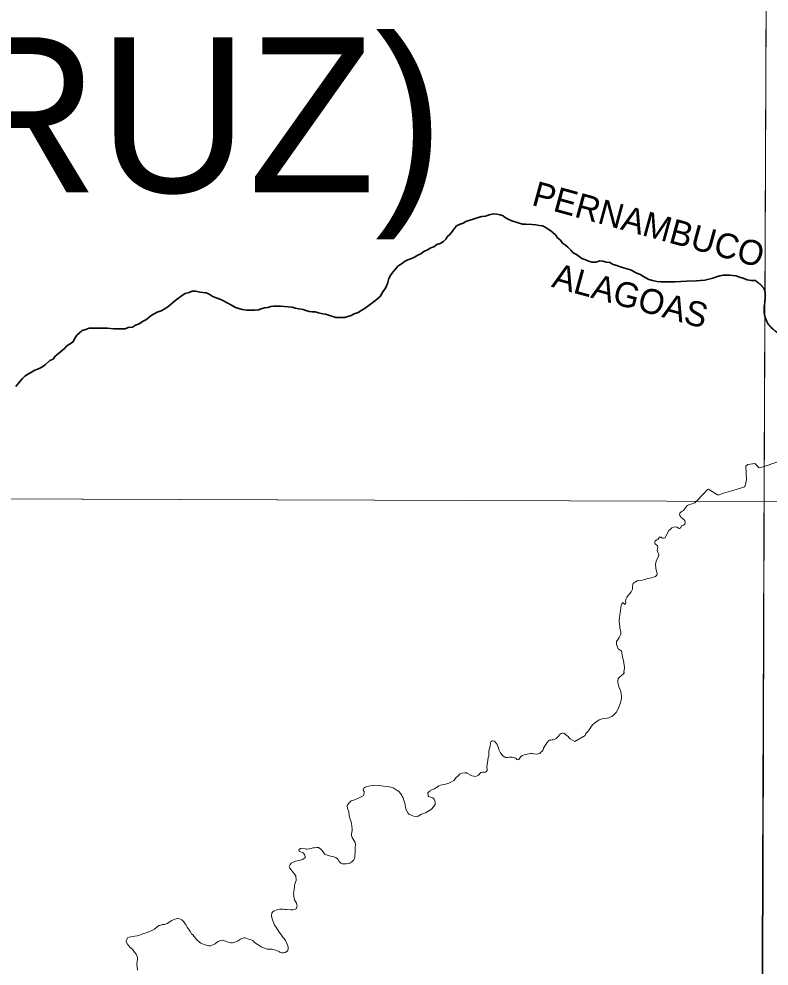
# Model space of a CAD drawing. Extents: x 553962 to 842807, y 8883888 to 9032388.
# Drawn here: x 594238 to 596656, y 8919494 to 8922544 of the extents above; entities that cross this region are included whole.
import ezdxf
from ezdxf.enums import TextEntityAlignment as Align

# ---------------------------------------------------------------- set-up
doc = ezdxf.new("R2010")
doc.units = 0
doc.header["$LTSCALE"] = 200
doc.linetypes.add('LONG_DASH_SHORT_DASH', pattern=[9.9, 6, -1.2, 1.5, -1.2])
doc.layers.add('6', color=7, linetype='Continuous', lineweight=13)

msp = doc.modelspace()

# ---------------------------------------------------------------- linework, layer by layer
at = {"layer": '6'}
for points in [[(585656.3, 8924738.8), (596655.5, 8924715.8), (596639.8, 8920989.8), (585645.8, 8921027.3)], [(607600.8, 8920952.4), (596639.8, 8920989.8), (596608.8, 8909934.4), (607569.8, 8909894.9)]]:
    msp.add_lwpolyline(points, close=True, dxfattribs=at)
for points in [[(596655.5, 8924715.8), (596593.3, 8909930.3), (596531.7, 8896026.7)], [(596581.2, 8921103.5), (596583.4, 8921058), (596577.4, 8921038.4), (596576.5, 8921036.9), (596546.9, 8921026.8), (596509.1, 8921016.7), (596491.7, 8921010.3), (596490, 8921010.8), (596472.1, 8921022.3), (596460.7, 8921029.2), (596459.6, 8921029.6), (596457.7, 8921028), (596445.2, 8921015.4), (596419.5, 8920988.9)], [(596684.4, 8921117.9), (596636.5, 8921101.1), (596623.7, 8921097.9), (596609.9, 8921111.7), (596587.7, 8921108.9), (596581.2, 8921103.5)], [(574684.9, 8921064.7), (596639.8, 8920989.8), (607636.3, 8920937.2), (626625.7, 8920820.5)], [(596419.5, 8920988.9), (596416.1, 8920985.5), (596411.6, 8920983.1), (596407.8, 8920981.7), (596399.5, 8920980), (596392.7, 8920976.5), (596389.8, 8920974.2), (596389.4, 8920973.2), (596388.5, 8920972.8), (596388, 8920971.8), (596387, 8920970.8), (596385.5, 8920968), (596383.2, 8920964.5), (596380.2, 8920960.7), (596376.2, 8920958.1), (596372.5, 8920956.2), (596369.6, 8920953.6), (596368.4, 8920952), (596367.4, 8920948.3), (596368.1, 8920946.1), (596368.2, 8920944.4), (596370, 8920941.5), (596371.9, 8920939.1), (596374.2, 8920937.3), (596377.3, 8920934.5), (596381, 8920931.9), (596384.8, 8920927.5), (596384.8, 8920927.5), (596385.6, 8920924.6), (596383.9, 8920916.4), (596383.6, 8920915.6), (596379.7, 8920913.5), (596373.2, 8920911.8), (596371.3, 8920906.5), (596370.2, 8920904.4), (596367.6, 8920903.1), (596364.1, 8920903.5), (596358.3, 8920907.2), (596357.3, 8920907.5), (596352.8, 8920907.7), (596347.5, 8920907.1), (596342.6, 8920904.7), (596337.1, 8920900), (596333.1, 8920895.9), (596322.9, 8920878.2)], [(596322.9, 8920878.2), (596321.8, 8920875.5), (596320.5, 8920873.2), (596315.8, 8920871.4), (596312.6, 8920871.3), (596310.4, 8920872.7), (596308.4, 8920874.5), (596303, 8920874.9), (596298.1, 8920868.6), (596293.7, 8920866.1), (596288.5, 8920862.6), (596287.3, 8920858.1), (596287.3, 8920855.8), (596289.2, 8920853.1), (596295.7, 8920846.8), (596296.2, 8920845.8), (596296.8, 8920842.9), (596295, 8920832), (596300.2, 8920819.4), (596299.3, 8920813.8), (596292.4, 8920797.3), (596290.7, 8920791.7), (596289.4, 8920786.3), (596290.7, 8920775), (596292.3, 8920769.4), (596293.4, 8920763.9), (596295.3, 8920758.3), (596294.3, 8920752.9), (596293.5, 8920751), (596289.7, 8920748.2), (596275.6, 8920744), (596269.9, 8920743.1), (596264.5, 8920741.9), (596258.8, 8920739.7), (596253.2, 8920738.4), (596247.6, 8920736.7), (596236.5, 8920735.2), (596230.9, 8920733.7), (596225.4, 8920731.3), (596218.8, 8920726.5), (596218.2, 8920725.5), (596216.7, 8920722.2), (596215.8, 8920715.7), (596215.7, 8920710.1), (596215.3, 8920707.1), (596211.6, 8920699.2), (596197.7, 8920682), (596193.8, 8920675.4), (596193.1, 8920667.7), (596194.2, 8920664.1), (596192.8, 8920660.7), (596192.2, 8920658.1), (596192, 8920658), (596185.8, 8920663.5), (596183.3, 8920663.3), (596181.1, 8920659.8), (596179.3, 8920654.3), (596178.1, 8920648.7), (596176.8, 8920637.8), (596175.7, 8920632), (596175.2, 8920626.1), (596173.4, 8920615.3), (596172.7, 8920609.8), (596172.8, 8920603.6), (596174.4, 8920586.9), (596175.3, 8920581.1), (596177.2, 8920575.1), (596177.8, 8920569.5), (596177.6, 8920563.3), (596177.3, 8920560), (596173.2, 8920551.4), (596169.7, 8920546), (596164.5, 8920539), (596163.8, 8920534.7), (596164.4, 8920529.3), (596165.8, 8920523.5), (596169.8, 8920515.6), (596179, 8920508.3), (596179.7, 8920507.3), (596181.2, 8920501.9), (596182.2, 8920495.7), (596184.6, 8920484.3), (596186.5, 8920477.5), (596189.9, 8920455.4)], [(596189.9, 8920455.4), (596189.5, 8920454.3), (596187.2, 8920440.2), (596187.2, 8920439.4), (596188.3, 8920437.7), (596188.3, 8920437.1), (596185.5, 8920433.8), (596181.5, 8920430.2), (596172.4, 8920423), (596169.5, 8920418.8), (596168.2, 8920412.8), (596168.7, 8920407.7), (596169.5, 8920402.7), (596172, 8920392.7), (596176.5, 8920381.4), (596178, 8920376.9), (596179.2, 8920371.6), (596180.6, 8920361.1), (596180.6, 8920356.3), (596179.6, 8920351.4), (596176.7, 8920340.8), (596168, 8920320.1), (596162.5, 8920310), (596158.8, 8920305.4), (596153.7, 8920300.7), (596148.8, 8920297.3), (596144, 8920294.9), (596139.2, 8920293.3), (596128.6, 8920290.9), (596118.2, 8920289.7), (596108.2, 8920286.6), (596097.6, 8920278.6)], [(596097.6, 8920278.6), (596087, 8920270.7), (596086.2, 8920270.4), (596080.9, 8920262.8), (596078.5, 8920257.9), (596076, 8920254.4), (596072.4, 8920250.1), (596065.8, 8920243.2), (596064.1, 8920240.6), (596063, 8920236.2), (596030, 8920216.7), (596014.6, 8920225.9), (596013.7, 8920226.2), (596013.1, 8920226.8), (596012.8, 8920227.7), (596010.9, 8920229.4), (596007.9, 8920232.8), (596000.2, 8920239.7), (595996.7, 8920242.2), (595992.4, 8920243.5), (595988.7, 8920243.2), (595985.4, 8920242.5), (595983.7, 8920241.8), (595981.6, 8920239.6), (595976.4, 8920232.6), (595973.2, 8920229.4), (595969.3, 8920226.3), (595963.4, 8920223.6), (595959.7, 8920222.4), (595955.7, 8920221.9), (595952, 8920221.1), (595948.5, 8920221.1), (595947.7, 8920220.8), (595944.7, 8920218.6), (595940.5, 8920213.8), (595940.1, 8920212.7), (595939.1, 8920212), (595936.7, 8920206.9)], [(595936.7, 8920206.9), (595936.6, 8920206.9), (595929.1, 8920195.6), (595929.2, 8920192.4), (595927.8, 8920190.1), (595924, 8920185.5), (595919.5, 8920180.9), (595916.5, 8920178.5), (595912.4, 8920177.2), (595907.3, 8920176.2), (595897.2, 8920177), (595891.9, 8920177.8), (595886.4, 8920177.8), (595881.6, 8920177.2), (595866.2, 8920173.5), (595861.1, 8920171.8), (595856.2, 8920168.8), (595848.9, 8920158.8), (595845, 8920158), (595843.1, 8920159.2), (595839.4, 8920163), (595833.5, 8920165.6), (595828.2, 8920166.5), (595818.6, 8920165.9), (595813.1, 8920165), (595806.4, 8920165.6), (595802.8, 8920167.3), (595797.3, 8920170.8), (595790.6, 8920180), (595786.8, 8920186.4), (595784.7, 8920191.3), (595784, 8920196.7), (595782.1, 8920201.6), (595779.5, 8920206.9), (595776.4, 8920211.9), (595772.8, 8920216), (595770, 8920218), (595764.9, 8920219.3), (595762.9, 8920219.2), (595760.1, 8920216.5), (595757.9, 8920212.1), (595756.5, 8920201.4), (595753, 8920186.6), (595752.3, 8920180.9), (595752.1, 8920171), (595750.8, 8920165.7), (595749.5, 8920155.6), (595748.2, 8920150.3), (595746.6, 8920135.4), (595747, 8920125.1), (595746.8, 8920123), (595744.1, 8920119), (595741.7, 8920117.9), (595733.7, 8920117.9), (595729, 8920117.3), (595726.8, 8920116.5), (595726.1, 8920116), (595719.5, 8920108.7), (595714.6, 8920105.7), (595709.3, 8920104.6), (595704.2, 8920104.7), (595697.4, 8920106.1), (595682.2, 8920114.9), (595680.4, 8920115.5), (595675.5, 8920115.9), (595665.3, 8920114.4), (595660.3, 8920112.3), (595658.1, 8920111)], [(595658.1, 8920111), (595655.6, 8920108.5), (595651.9, 8920104.2), (595647.8, 8920100.6), (595639.3, 8920091), (595632.7, 8920087), (595623.2, 8920082.6), (595617.5, 8920080.8), (595612.7, 8920078.9), (595606.8, 8920078.2), (595597.1, 8920075.8), (595591.6, 8920073.9), (595586.7, 8920071), (595581.7, 8920067.6), (595577.1, 8920064.8), (595571.5, 8920062.6), (595561.7, 8920056.4), (595561.7, 8920056.4), (595556.2, 8920051.1)], [(595556.2, 8920051.1), (595556.8, 8920041.8), (595557.1, 8920040.8), (595558.3, 8920039.9), (595568.7, 8920036.2), (595571.6, 8920035), (595576.8, 8920030.7), (595578.9, 8920025.4), (595579.7, 8920020.2), (595579.8, 8920016.6), (595579.2, 8920014.4), (595568.5, 8919999.7), (595567.3, 8919998.5), (595548.1, 8919986.8), (595541.1, 8919985.3), (595535.4, 8919982.4), (595524.6, 8919976), (595518.6, 8919974.3), (595513.3, 8919975), (595502.3, 8919979.2), (595495.2, 8919983.1), (595491.5, 8919987.2), (595486.8, 8919994.6), (595485.2, 8920000.2), (595484.5, 8920006.3), (595481.8, 8920018), (595479.4, 8920024.2), (595478.1, 8920030.1), (595476.1, 8920035.8), (595474.8, 8920037.4), (595472.3, 8920042.5), (595468.9, 8920048.1), (595462.9, 8920056.2), (595457.2, 8920059.5), (595444.2, 8920067.7), (595436.6, 8920069.9), (595431.2, 8920071), (595425.4, 8920071.8), (595413.3, 8920072.9), (595407.1, 8920073.8), (595395.5, 8920074.6), (595383.1, 8920075.9), (595377.1, 8920075.5), (595365.3, 8920073.2), (595359.7, 8920071.7), (595353.5, 8920068.5), (595349.8, 8920066.3), (595348.4, 8920064.4), (595347.6, 8920062.5), (595348.1, 8920060.6), (595350.5, 8920055.3), (595350.7, 8920050.2), (595349.1, 8920044.4), (595347.4, 8920041.8), (595332.8, 8920034.6), (595319.8, 8920029.3), (595308.8, 8920025.2), (595303.6, 8920020.4), (595296.8, 8920012.5), (595296.3, 8920010.1), (595296.8, 8920002), (595298.6, 8919998.5), (595301.1, 8919990.6), (595302.4, 8919978.8), (595303.5, 8919972.9), (595306.1, 8919966.4), (595309.8, 8919954.2), (595311.2, 8919942.8), (595312.2, 8919936.4), (595312.2, 8919930.6), (595310.5, 8919919.3), (595310.5, 8919914.1), (595312, 8919907.4), (595321.5, 8919891.2), (595322.7, 8919885.4), (595322.1, 8919874.5), (595322.3, 8919868.3), (595321.6, 8919856.8), (595320.8, 8919850.8), (595321, 8919844.9), (595319.8, 8919839.6), (595317.8, 8919835.8), (595315.7, 8919833.1), (595311, 8919828.8), (595304.7, 8919824.7), (595293.7, 8919822.5), (595287.7, 8919822.5), (595281.7, 8919822.9), (595279.6, 8919823.3), (595276.1, 8919825.3), (595270.4, 8919830.6), (595265.5, 8919837.5), (595259.1, 8919843.4), (595253.4, 8919845.2), (595241.8, 8919847.7), (595235.8, 8919849.4), (595229.3, 8919851.8), (595224.2, 8919853.9), (595221.7, 8919855.6), (595215.5, 8919865.8), (595211.5, 8919869.9)], [(595211.5, 8919869.9), (595211.5, 8919869.9), (595203.4, 8919875.3), (595196.7, 8919875.5), (595191.1, 8919874.5), (595185.1, 8919873.9), (595179.1, 8919872.2), (595173.5, 8919871.2), (595167, 8919870.5), (595163.5, 8919870.5), (595160.9, 8919871.1), (595149.3, 8919873), (595145.9, 8919872.6), (595141.2, 8919869.2), (595140.4, 8919866.2), (595140.9, 8919864.8), (595142, 8919862.9), (595154.1, 8919858.3), (595158.4, 8919853), (595159.9, 8919850), (595160.5, 8919846.3), (595160.3, 8919843.4), (595158.2, 8919840.8), (595152.4, 8919836.5), (595141.6, 8919833.3), (595135.4, 8919832.3), (595129.5, 8919831.1), (595122.5, 8919828.4), (595116, 8919824.6), (595113.1, 8919821.6), (595112.2, 8919820.4), (595109.5, 8919814.4), (595109.6, 8919812.9), (595111.6, 8919808.8), (595130.3, 8919784.6), (595131.4, 8919769.3), (595127.8, 8919758.5), (595126.5, 8919753.3), (595126, 8919748), (595123.7, 8919733.2), (595123.5, 8919727.1), (595123.7, 8919722.3), (595124.3, 8919717.4), (595126.6, 8919707.1), (595129.1, 8919701.7), (595132.3, 8919696.5), (595134.2, 8919691.2), (595134.9, 8919686.4), (595133.1, 8919680.8), (595132.3, 8919679.5), (595128.7, 8919677), (595125.3, 8919675.6), (595120.4, 8919674.8), (595115, 8919674.6), (595100.3, 8919676.1), (595094.8, 8919676.1), (595089.5, 8919676.5), (595084.5, 8919676.3), (595079.2, 8919676.5), (595069.2, 8919674.8), (595059.4, 8919670.2), (595055.8, 8919667.6), (595053.5, 8919663.7), (595052, 8919657.7), (595052.1, 8919654.1), (595055.6, 8919642.4), (595057.9, 8919637.1), (595059.3, 8919631.8), (595061.3, 8919625.8), (595063.1, 8919624.4), (595064.1, 8919622.7), (595069.5, 8919614.9), (595072.4, 8919609.9), (595076.3, 8919605.2), (595080.2, 8919598.6), (595084.2, 8919593.5), (595088.7, 8919586.8), (595092.6, 8919582.8), (595096.9, 8919576.3), (595099.5, 8919571.6), (595104.2, 8919560.8), (595105.8, 8919556), (595106, 8919550.3), (595104.9, 8919544.2), (595104.4, 8919543.4), (595101.4, 8919540.4), (595096.4, 8919537.1), (595091.3, 8919536.3), (595085.6, 8919536.5), (595079.3, 8919538.1), (595076.2, 8919540.5), (595069.8, 8919543.9), (595053.4, 8919547.8), (595038.5, 8919547.9)], [(595038.5, 8919547.9), (595038.5, 8919547.9), (595023.6, 8919553.8), (595021, 8919554), (594997.1, 8919569.7), (594992.7, 8919574.4), (594988.3, 8919577.5), (594983.2, 8919579.3), (594977.9, 8919580.7), (594967.4, 8919584.3), (594967.4, 8919584.3), (594962.5, 8919584), (594957.2, 8919582.7), (594952.2, 8919580.4), (594942.3, 8919574.2), (594931.7, 8919569.5), (594926.3, 8919568.6), (594921, 8919568.3), (594916.2, 8919569.5), (594900.8, 8919574.8), (594896.1, 8919576.2), (594890.9, 8919576.6), (594889, 8919576.3), (594880.2, 8919572.8), (594875.3, 8919569.6), (594870.1, 8919565.6), (594866.2, 8919563.1), (594861.2, 8919560.8), (594855.5, 8919559.2), (594850.6, 8919559), (594845, 8919559.4), (594835.2, 8919562.7), (594830.2, 8919564.8), (594824.9, 8919567.4), (594820.3, 8919570.2), (594811.4, 8919577.8), (594807, 8919583.8), (594798.1, 8919593.9), (594794.3, 8919597.8), (594791.6, 8919603.4), (594788, 8919608), (594780.1, 8919619.3), (594777, 8919624.9), (594773.5, 8919629.2), (594769.1, 8919635.6), (594765.6, 8919640.1), (594763.3, 8919642.3), (594758.6, 8919644.9), (594751.6, 8919646.6), (594748.7, 8919646.7), (594741, 8919644.8), (594731.3, 8919640.1), (594716.2, 8919630.9), (594710.7, 8919628.3), (594708.7, 8919627.7), (594700.3, 8919627), (594695.4, 8919625.8), (594690.4, 8919623.9), (594685.2, 8919620.5), (594675.3, 8919612.9), (594666.2, 8919607.6), (594660.5, 8919605.2), (594645.4, 8919599.5), (594640.1, 8919598), (594635, 8919595.8)], [(594635, 8919595.8), (594624.9, 8919592.5), (594619.4, 8919591.1), (594604.2, 8919588.8), (594593.8, 8919586.4), (594587.8, 8919584), (594585.7, 8919579.6), (594584.3, 8919574.8), (594584.1, 8919571.4), (594587.7, 8919564.4), (594590.8, 8919560), (594596.2, 8919553.6), (594605.1, 8919547.1), (594605.3, 8919546), (594606.5, 8919545.2), (594610.9, 8919538.4), (594616.3, 8919531.4), (594619.9, 8919521.3), (594620.2, 8919515.6), (594618.5, 8919500.2), (594620, 8919480)]]:
    msp.add_lwpolyline(points, dxfattribs=at)
at = {"layer": '6', "linetype": 'LONG_DASH_SHORT_DASH', "lineweight": 35}
for points in [[(595503.7, 8921771.9), (595513.3, 8921776.4), (595523.8, 8921783.5), (595533.3, 8921787.6), (595542.8, 8921794.6), (595554.8, 8921799.7), (595565.9, 8921806.8), (595575.4, 8921810.3), (595584.9, 8921816.9), (595595.4, 8921821), (595607, 8921827), (595613.5, 8921834.6), (595619.5, 8921842.7), (595626.5, 8921849.7), (595635, 8921860.3), (595640.5, 8921868.3), (595647.9, 8921877.9), (595660, 8921882.5), (595669.5, 8921886.5), (595678, 8921891.1), (595709.1, 8921900.8), (595718.1, 8921904.3), (595730.2, 8921907.9), (595742.2, 8921908.9), (595753.8, 8921913), (595767.3, 8921916.1), (595779.9, 8921915.6), (595789.4, 8921912.7), (595799, 8921909.2), (595806.5, 8921903.2), (595816.6, 8921897.7), (595827.1, 8921893.8), (595861.3, 8921882.9), (595871.9, 8921882.9), (595892.5, 8921882), (595904, 8921881.1), (595916.1, 8921878.1), (595925.6, 8921877.1), (595934.7, 8921873.7), (595943.7, 8921867.2), (595952.3, 8921861.7), (595960.3, 8921855.2), (595968.4, 8921847.7), (595974, 8921838.7), (595983.5, 8921831.2), (595990.1, 8921821.7), (596000.2, 8921815.7), (596007.7, 8921809.2), (596016.8, 8921798.7), (596024.9, 8921790.7), (596035.4, 8921784.8), (596052.1, 8921771.8), (596061.6, 8921768.8), (596073.7, 8921763.3), (596085.2, 8921760.4), (596097.3, 8921760.4), (596110.3, 8921764.5), (596119.9, 8921763.6), (596131.4, 8921760.1), (596142.5, 8921759.1), (596153.6, 8921753.2), (596165.6, 8921749.7), (596176.7, 8921745.2), (596186.7, 8921741.8), (596208.8, 8921735.8), (596232, 8921724.4), (596241.6, 8921720.9), (596249.1, 8921714.9), (596268.7, 8921704.5), (596279.8, 8921701), (596294.3, 8921698.1), (596306.9, 8921697.1), (596320, 8921696.7), (596353.6, 8921696.8), (596389.2, 8921699), (596420.4, 8921700.1), (596448.5, 8921702.3), (596474.6, 8921709.4), (596486.1, 8921713.5), (596497.6, 8921717), (596508.2, 8921718.1), (596528.7, 8921718.2), (596538.8, 8921717.7), (596549.8, 8921716.3), (596560.4, 8921712.3), (596572.5, 8921708.8), (596585, 8921703.4), (596598.6, 8921701.4), (596611.6, 8921701.5)], [(594412.5, 8921504.4), (594417, 8921514), (594424.5, 8921525.1), (594441.5, 8921540.7), (594453.5, 8921543.8), (594464, 8921547.8), (594495.2, 8921548), (594509.2, 8921547.5), (594523.3, 8921547.6), (594543.9, 8921545.7), (594569, 8921545.8), (594580.6, 8921546.3), (594590.1, 8921549.9), (594603.7, 8921551.5), (594614.2, 8921558.1), (594625.2, 8921562.1), (594636.2, 8921569.7), (594646.8, 8921574.3), (594657.3, 8921581.8), (594664.3, 8921588.9), (594683.8, 8921599), (594696.4, 8921604.1), (594705.9, 8921609.2), (594718.4, 8921616.8), (594744.4, 8921639), (594765, 8921654.6), (594774, 8921659.2), (594786.5, 8921662.7), (594796.6, 8921666.8), (594808.1, 8921666.8), (594820.7, 8921664.4), (594841.3, 8921661.5), (594851.3, 8921657), (594860.9, 8921651), (594870.5, 8921647.1), (594883, 8921642.6), (594893.1, 8921638.6), (594925.8, 8921621.2), (594936.4, 8921614.7), (594958, 8921608.3), (594972.1, 8921605.8), (594986.1, 8921605.9), (594998.2, 8921606.4), (595010.2, 8921606.5), (595019.3, 8921610.1), (595029.8, 8921613.6), (595040.8, 8921614.7), (595049.9, 8921618.2), (595059.9, 8921618.8), (595070, 8921618.8), (595081.5, 8921618.4), (595106.1, 8921616.5), (595118.7, 8921616), (595128.2, 8921612.6), (595140.3, 8921610.1), (595153.9, 8921608.2), (595162.9, 8921604.7), (595173.5, 8921601.7), (595183, 8921600.8), (595193.1, 8921600.3), (595203.6, 8921596.8), (595217.2, 8921593.9), (595226.7, 8921592.9), (595259.9, 8921582), (595287, 8921582.1), (595309.1, 8921588.3), (595319.1, 8921594.3), (595331.2, 8921597.9), (595343.7, 8921605.5), (595354.2, 8921612.6), (595388.8, 8921638.3), (595402.3, 8921649.4), (595410.8, 8921664.5), (595419.2, 8921676.6), (595423.7, 8921686.2), (595427.2, 8921695.2), (595430.2, 8921707.8), (595437.2, 8921719.8), (595444.2, 8921729.4), (595460.7, 8921748.6), (595469.7, 8921754.1), (595481.2, 8921762.2), (595491.7, 8921767.8), (595503.7, 8921771.9)], [(594228.2, 8921360.5), (594241.7, 8921377.7), (594249.7, 8921386.2), (594257.7, 8921393.3), (594269.2, 8921400.9), (594278.7, 8921405.9), (594289.8, 8921413), (594300.8, 8921417.1), (594311.8, 8921422.1), (594322.3, 8921429.7), (594337.9, 8921443.3), (594348.4, 8921448.4), (594354.9, 8921457.5), (594365.9, 8921466.1), (594384.9, 8921482.7), (594392.4, 8921491.3), (594401.5, 8921496.3), (594412.5, 8921504.4)]]:
    msp.add_lwpolyline(points, dxfattribs=at)
msp.add_spline([(596611.2, 8921701.9), (596639.9, 8921673.2), (596639.9, 8921601.6), (596665.6, 8921547.2), (596711.4, 8921507.1), (596720, 8921478.5), (596734.3, 8921432.6), (596788.7, 8921312.3), (596811.6, 8921237.9), (596823.1, 8921194.9), (596828.8, 8921163.4), (596788.7, 8921134.8), (596705.7, 8921123.3), (596700, 8921083.2), (596772.7, 8920987.6)], degree=3, dxfattribs=at)

# ---------------------------------------------------------------- texts
at = {"layer": '6'}
msp.add_text('(POÇO DA CRUZ)', height=500, dxfattribs=at).set_placement((590036.9, 8921984.9))
for s, p in [('PERNAMBUCO', (596257.1, 8921844)), ('ALAGOAS', (596198.5, 8921614.1))]:
    msp.add_text(s, height=80, rotation=344.671, dxfattribs=at).set_placement(p, align=Align.CENTER)

doc.saveas('drawing.dxf')
